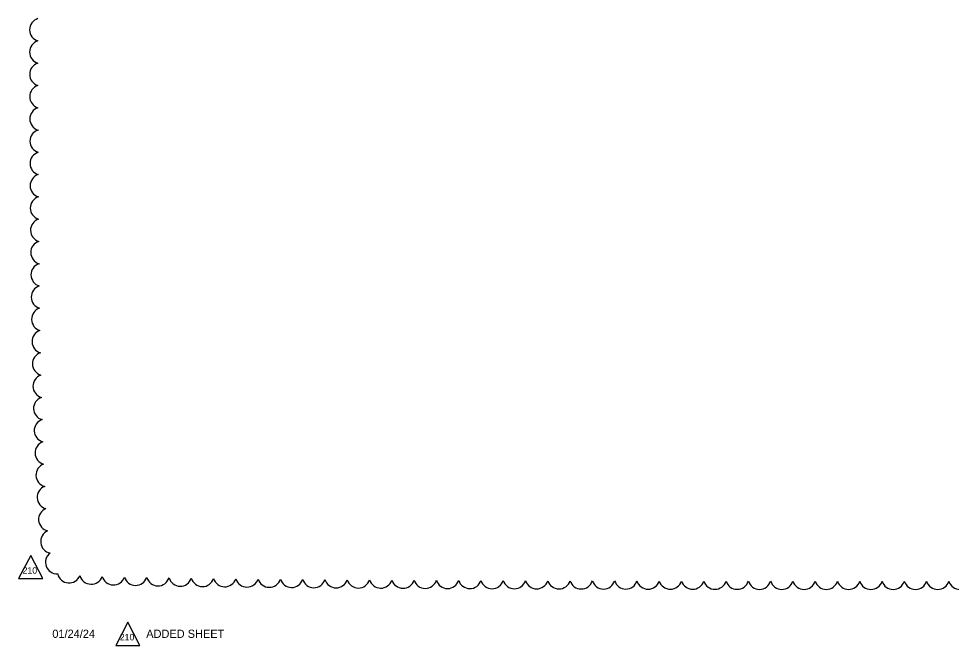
# Model space of a CAD drawing. Extents: x -811 to -790, y -2284 to -2178.
# Drawn here: x -811.07 to -803.16, y -2283.85 to -2278.54 of the extents above; entities that cross this region are included whole.
import ezdxf

# ---------------------------------------------------------------- set-up
doc = ezdxf.new("R2010")
doc.units = 0
doc.layers.add('ScratchEle_dp', color=7, linetype='Continuous')

msp = doc.modelspace()

# ---------------------------------------------------------------- linework, layer by layer
at = {"layer": 'ScratchEle_dp'}
for points in [[(-810.9694, -2283.0907), (-811.0715, -2283.2874), (-810.8673, -2283.2874)], [(-810.1449, -2283.6566), (-810.247, -2283.8533), (-810.0428, -2283.8533)]]:
    msp.add_lwpolyline(points, close=True, dxfattribs=at)
for centre, start, end in [((-810.8794, -2278.6311), 107.52584, 252.52584), ((-810.8792, -2278.82), 107.56719, 252.56719), ((-810.8789, -2279.009), 107.61129, 252.61129), ((-810.8785, -2279.198), 107.65843, 252.65843), ((-810.8779, -2279.387), 107.709, 252.709), ((-810.8771, -2279.5759), 107.76343, 252.76343), ((-810.8761, -2279.7649), 107.82224, 252.82224), ((-810.8749, -2279.9539), 107.88605, 252.88605), ((-810.8736, -2280.1428), 107.95561, 252.95561), ((-810.8719, -2280.3318), 108.03183, 253.03183), ((-810.87, -2280.5207), 108.11586, 253.11586), ((-810.8679, -2280.7097), 108.20912, 253.20912), ((-810.8653, -2280.8986), 108.31345, 253.31345), ((-810.8625, -2281.0875), 108.43121, 253.43121), ((-810.8592, -2281.2764), 108.56556, 253.56556), ((-810.8554, -2281.4653), 108.72081, 253.72081), ((-810.8511, -2281.6541), 108.903, 253.903), ((-810.8461, -2281.843), 109.12096, 254.12096), ((-810.8403, -2282.0317), 109.38818, 254.38818), ((-810.8335, -2282.2204), 109.72657, 254.72657), ((-810.8255, -2282.409), 110.17469, 255.17469), ((-810.8156, -2282.5974), 110.80877, 255.80877), ((-810.8031, -2282.7855), 111.80931, 256.80931), ((-810.7858, -2282.9726), 113.77584, 258.77584), ((-810.7447, -2283.1485), 127.48462, 272.48462), ((-810.644, -2283.2249), 193.17348, 338.17348), ((-810.4565, -2283.2354), 195.39639, 340.39639), ((-810.2679, -2283.2414), 195.97806, 340.97806), ((-810.0791, -2283.2459), 196.28744, 341.28744), ((-809.8902, -2283.2496), 196.48754, 341.48754), ((-809.7013, -2283.2527), 196.63065, 341.63065), ((-809.5124, -2283.2554), 196.73959, 341.73959), ((-809.3235, -2283.2577), 196.8261, 341.8261), ((-809.1345, -2283.2598), 196.89697, 341.89697), ((-808.9455, -2283.2617), 196.95641, 341.95641), ((-808.7566, -2283.2634), 197.0072, 342.0072), ((-808.5676, -2283.265), 197.05125, 342.05125), ((-808.3786, -2283.2664), 197.08993, 342.08993), ((-808.1897, -2283.2677), 197.12425, 342.12425), ((-808.0007, -2283.2689), 197.15498, 342.15498), ((-807.8117, -2283.27), 197.18269, 342.18269), ((-807.6227, -2283.271), 197.20786, 342.20786), ((-807.4337, -2283.2719), 197.23085, 342.23085), ((-807.2447, -2283.2728), 197.25195, 342.25195), ((-807.0557, -2283.2735), 197.27142, 342.27142), ((-806.8667, -2283.2743), 197.28945, 342.28945), ((-806.6778, -2283.2749), 197.30621, 342.30621), ((-806.4888, -2283.2756), 197.32184, 342.32184), ((-806.2998, -2283.2761), 197.33647, 342.33647), ((-806.1108, -2283.2766), 197.3502, 342.3502), ((-805.9218, -2283.2771), 197.36311, 342.36311), ((-805.7328, -2283.2775), 197.37529, 342.37529), ((-805.5438, -2283.2779), 197.3868, 342.3868), ((-805.3548, -2283.2783), 197.3977, 342.3977), ((-805.1658, -2283.2786), 197.40804, 342.40804), ((-804.9768, -2283.2789), 197.41787, 342.41787), ((-804.7878, -2283.2791), 197.42723, 342.42723), ((-804.5988, -2283.2794), 197.43616, 342.43616), ((-804.4098, -2283.2796), 197.44468, 342.44468), ((-804.2208, -2283.2797), 197.45283, 342.45283), ((-804.0318, -2283.2799), 197.46064, 342.46064), ((-803.8428, -2283.28), 197.46812, 342.46812), ((-803.6538, -2283.2801), 197.4753, 342.4753), ((-803.4648, -2283.2802), 197.4822, 342.4822), ((-803.2759, -2283.2802), 197.48884, 342.48884), ((-803.0869, -2283.2802), 197.49523, 342.49523)]:
    msp.add_arc(centre, 0.0991, start, end, dxfattribs=at)

# ---------------------------------------------------------------- texts
for s, height, p in [('210', 0.0551, (-811.038, -2283.2452)), ('01/24/24', 0.0696, (-810.7859, -2283.7898)), ('ADDED SHEET', 0.0696, (-809.9894, -2283.7898)), ('210', 0.0551, (-810.2135, -2283.8111))]:
    msp.add_text(s, height=height, dxfattribs=at).set_placement(p)

doc.saveas('drawing.dxf')
